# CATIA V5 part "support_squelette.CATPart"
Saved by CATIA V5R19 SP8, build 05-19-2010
Part number: support2
Publications: "distance_ventouses", "longueur_bielles", "longueur_support", "largeur_support", "epaisseur_support", "hauteur_ventouse"
Bounding box of the stored display mesh (mm): x -262.398 to 250, y -100 to 100, z -10 to 0
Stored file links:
  G:\EU_thinkMotion\CFAO_2010\SIL_groupe1\SIL_groupe1\A reprendre\fbruguiere\fbruguiere\fbruguiere\support_squelette.CATPart
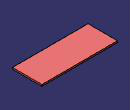
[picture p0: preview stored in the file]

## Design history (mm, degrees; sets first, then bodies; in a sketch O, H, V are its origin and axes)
Parameters
  distance_ventouses = 300
  longueur_bielles = 600
  longueur_support = 500
  largeur_support = 200
  epaisseur_support = 10
  hauteur_ventouse = 80
Body1 (main body)
  Sketch1 on xy-plane, origin (0, 0, 0), H (1, 0, 0), V (0, 1, 0)
    point P1 (60, 0)
    point P2 (-60, 0)
    point P3 (0, 20)
    coincidence: P1 H, P2 H, P3 V
  Sketch2 on xy-plane, origin (0, 0, 0), H (1, 0, 0), V (0, 1, 0)
    line L1 (250, 100) -> (250, -100)
    line L2 (250, -100) -> (-262.3977, -100)
    line L3 (-262.3977, -100) -> (-262.3977, 100)
    line L4 (-262.3977, 100) -> (250, 100)
    reference intersected line E1 through (0, 0) direction (-1, 0) from zx-plane
    reference intersected line E2 through (0, 0) direction (0, 1) from yz-plane
    distance E1 L2 = 100 {= largeur_support *1mm/2}
    distance L1 E2 = 250 {= longueur_support *1mm/2}
    vertical: L1 V, L3 V
    horizontal: L2 H
  Pad1: profile Sketch2, direction (0, 0, -1), length 10 {= epaisseur_support *1mm}
  Sketch3 on zx-plane, origin (0, 0, 0), H (-1, 0, 0), V (0, 0, 1)
  Sketch4 on zx-plane, origin (0, 0, 0), H (-1, 0, 0), V (0, 0, 1)
    point P1 (-150, 0)
    line L1 (-150, 0) -> (-150, 80)
    line L2 (-150, 80) -> (0, 660.9475)
    point P3 (0, 660.9475)
    line L3 (0, 660.9475) -> (150, 80)
    line L4 (150, 80) -> (150, 0)
    point P5 (150, 0)
    reference intersected line E1 through (0, 0) direction (0, -1) from yz-plane
    reference projected point E2 (0, 0) from Sketch1.P3
    distance L1 E1 = 150 {= distance_ventouses *1mm/2}
    distance E2 L4 = 150 {= distance_ventouses *1mm/2}
    length L4 = 80 {= hauteur_ventouse *1mm}
    length L1 = 80 {= hauteur_ventouse *1mm}
    length L3 = 600 {= longueur_bielles *1mm}
    coincidence: P1 H, P3 V, P5 H
    vertical: L1 V, L4 V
